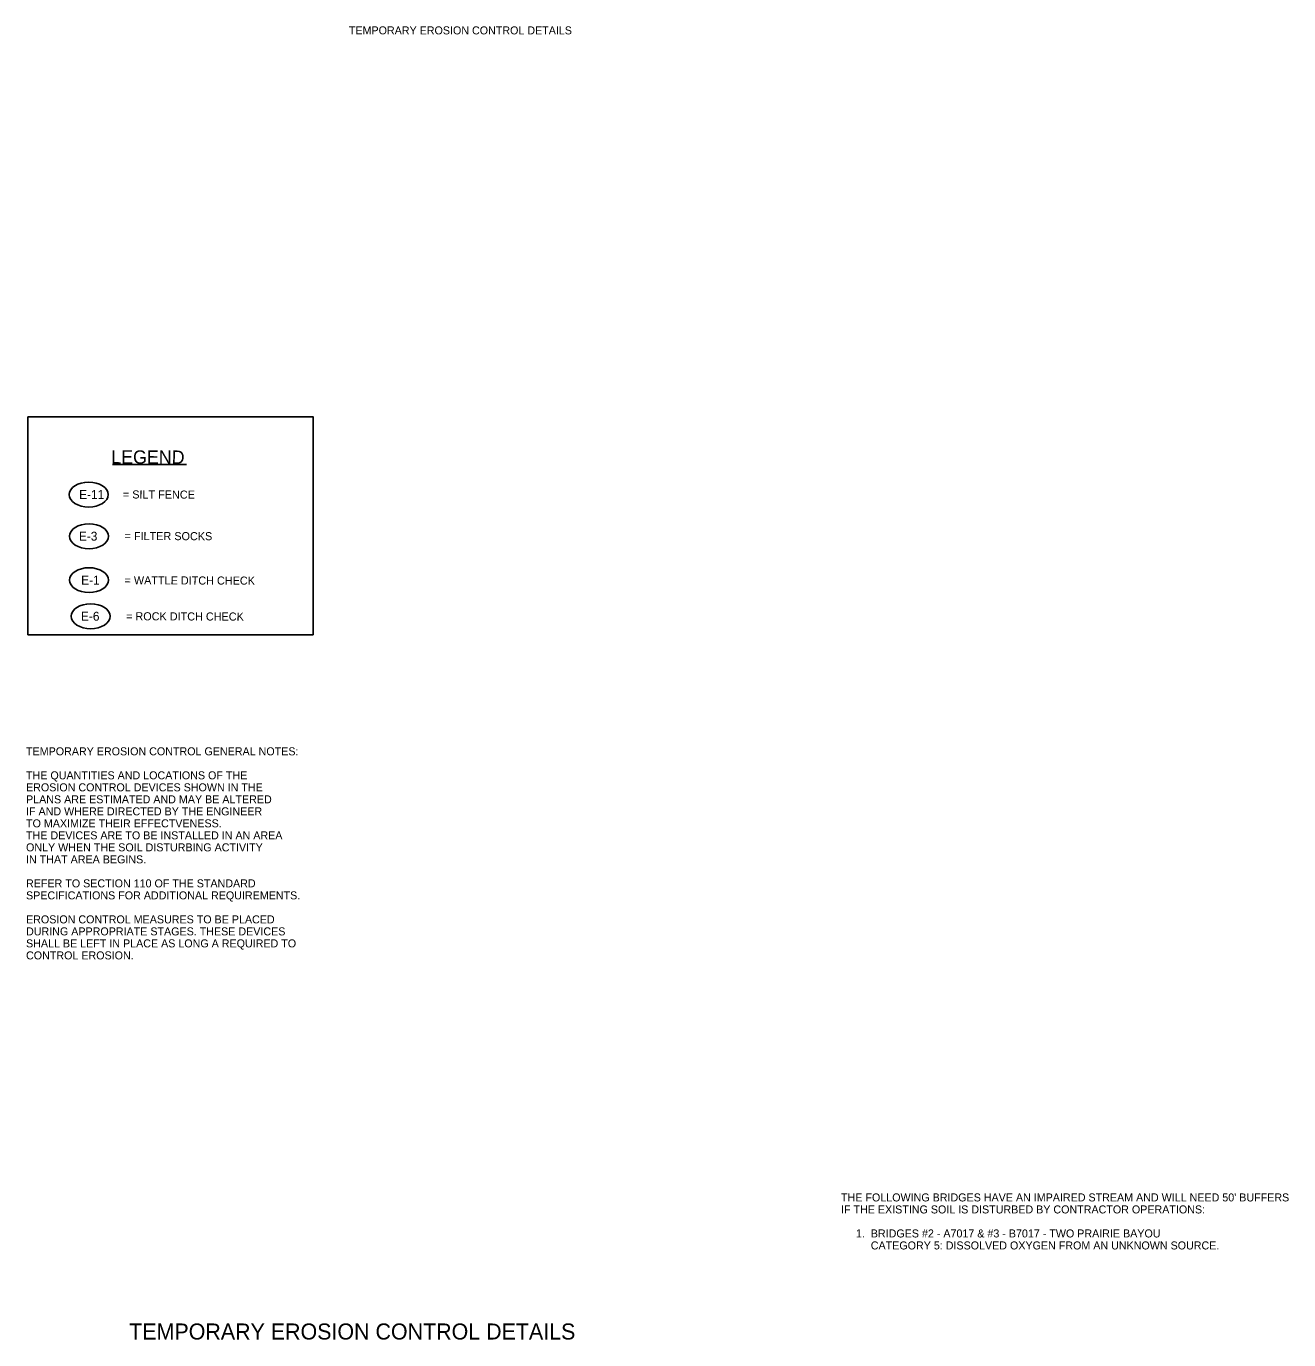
# Model space of a CAD drawing. Extents: x 1929624 to 1932607, y 596315 to 605533.
# Drawn here: x 1931661 to 1932607, y 604548 to 605533 of the extents above; entities that cross this region are included whole.
import ezdxf

# ---------------------------------------------------------------- set-up
doc = ezdxf.new("R2010")
doc.units = 0
for name, color, linetype in [('Default', 7, 'Continuous'), ('R_Border', 7, 'Continuous'), ('R_Border Prem', 7, 'Continuous')]:
    doc.layers.add(name, color=color, linetype=linetype)

msp = doc.modelspace()

# ---------------------------------------------------------------- linework, layer by layer
at = {"layer": 'R_Border'}
msp.add_line((1931725.56, 605204.24), (1931781.07, 605204.24), dxfattribs=at)
msp.add_lwpolyline([(1931662.33, 605240.07), (1931875.97, 605240.07), (1931875.97, 605076.56), (1931662.33, 605076.56)], close=True, dxfattribs=at)
for centre in [(1931707.88, 605181.67), (1931708.1, 605150.41), (1931708.1, 605117.51), (1931709.32, 605090.41)]:
    msp.add_ellipse(centre, major_axis=(14.6, 0), ratio=0.638788, dxfattribs=at)

# ---------------------------------------------------------------- texts
at = {"layer": 'Default'}
for s, height, p in [('LEGEND', 10, (1931724.71, 605204.87)), ('= SILT FENCE', 6.075, (1931733.48, 605178.75)), ('= FILTER SOCKS', 6.075, (1931734.76, 605147.6)), ('= WATTLE DITCH CHECK', 6.075, (1931734.7, 605114.38)), ('= ROCK DITCH CHECK', 6.075, (1931735.87, 605087.41))]:
    msp.add_text(s, height=height, rotation=359.82713, dxfattribs=at).set_placement(p)
at = {"layer": 'R_Border'}
for s, p in [('E-11', (1931700.66, 605178.4)), ('E-3', (1931700.49, 605147.13)), ('E-1', (1931702.2, 605114.23)), ('E-6', (1931702.05, 605087.13))]:
    msp.add_text(s, height=6.663, rotation=360, dxfattribs=at).set_placement(p)
for s, height, p in [('TEMPORARY EROSION CONTROL GENERAL NOTES:', 6, (1931660.88, 604986.16)), ('THE QUANTITIES AND LOCATIONS OF THE', 6, (1931660.88, 604968.16)), ('EROSION CONTROL DEVICES SHOWN IN THE ', 6, (1931660.88, 604959.16)), ('PLANS ARE ESTIMATED AND MAY BE ALTERED ', 6, (1931660.88, 604950.16)), ('IF AND WHERE DIRECTED BY THE ENGINEER ', 6, (1931660.88, 604941.16)), ('TO MAXIMIZE THEIR EFFECTVENESS. ', 6, (1931660.88, 604932.16)), ('THE DEVICES ARE TO BE INSTALLED IN AN AREA ', 6, (1931660.88, 604923.16)), ('ONLY WHEN THE SOIL DISTURBING ACTIVITY', 6, (1931660.88, 604914.16)), ('IN THAT AREA BEGINS.', 6, (1931660.88, 604905.16)), ('REFER TO SECTION 110 OF THE STANDARD ', 6, (1931660.88, 604887.16)), ('SPECIFICATIONS FOR ADDITIONAL REQUIREMENTS.', 6, (1931660.88, 604878.16)), ('EROSION CONTROL MEASURES TO BE PLACED', 6, (1931660.88, 604860.16)), ('DURING APPROPRIATE STAGES. THESE DEVICES', 6, (1931660.88, 604851.16)), ('SHALL BE LEFT IN PLACE AS LONG A REQUIRED TO ', 6, (1931660.88, 604842.16)), ('CONTROL EROSION.', 6, (1931660.88, 604833.16)), ("THE FOLLOWING BRIDGES HAVE AN IMPAIRED STREAM AND WILL NEED 50' BUFFERS", 6, (1932271.71, 604651.7)), ('IF THE EXISTING SOIL IS DISTURBED BY CONTRACTOR OPERATIONS:', 6, (1932271.71, 604642.7)), ('     1.  BRIDGES #2 - A7017 & #3 - B7017 - TWO PRAIRIE BAYOU ', 6, (1932271.71, 604624.7)), ('          CATEGORY 5: DISSOLVED OXYGEN FROM AN UNKNOWN SOURCE.', 6, (1932271.71, 604615.7)), ('TEMPORARY EROSION CONTROL DETAILS', 12, (1931738.22, 604548.18))]:
    msp.add_text(s, height=height, dxfattribs=at).set_placement(p)
at = {"layer": 'R_Border Prem'}
msp.add_text('TEMPORARY EROSION CONTROL DETAILS ', height=6, rotation=359.99339, dxfattribs=at).set_placement((1931902.85, 605526.69))

doc.saveas('drawing.dxf')
